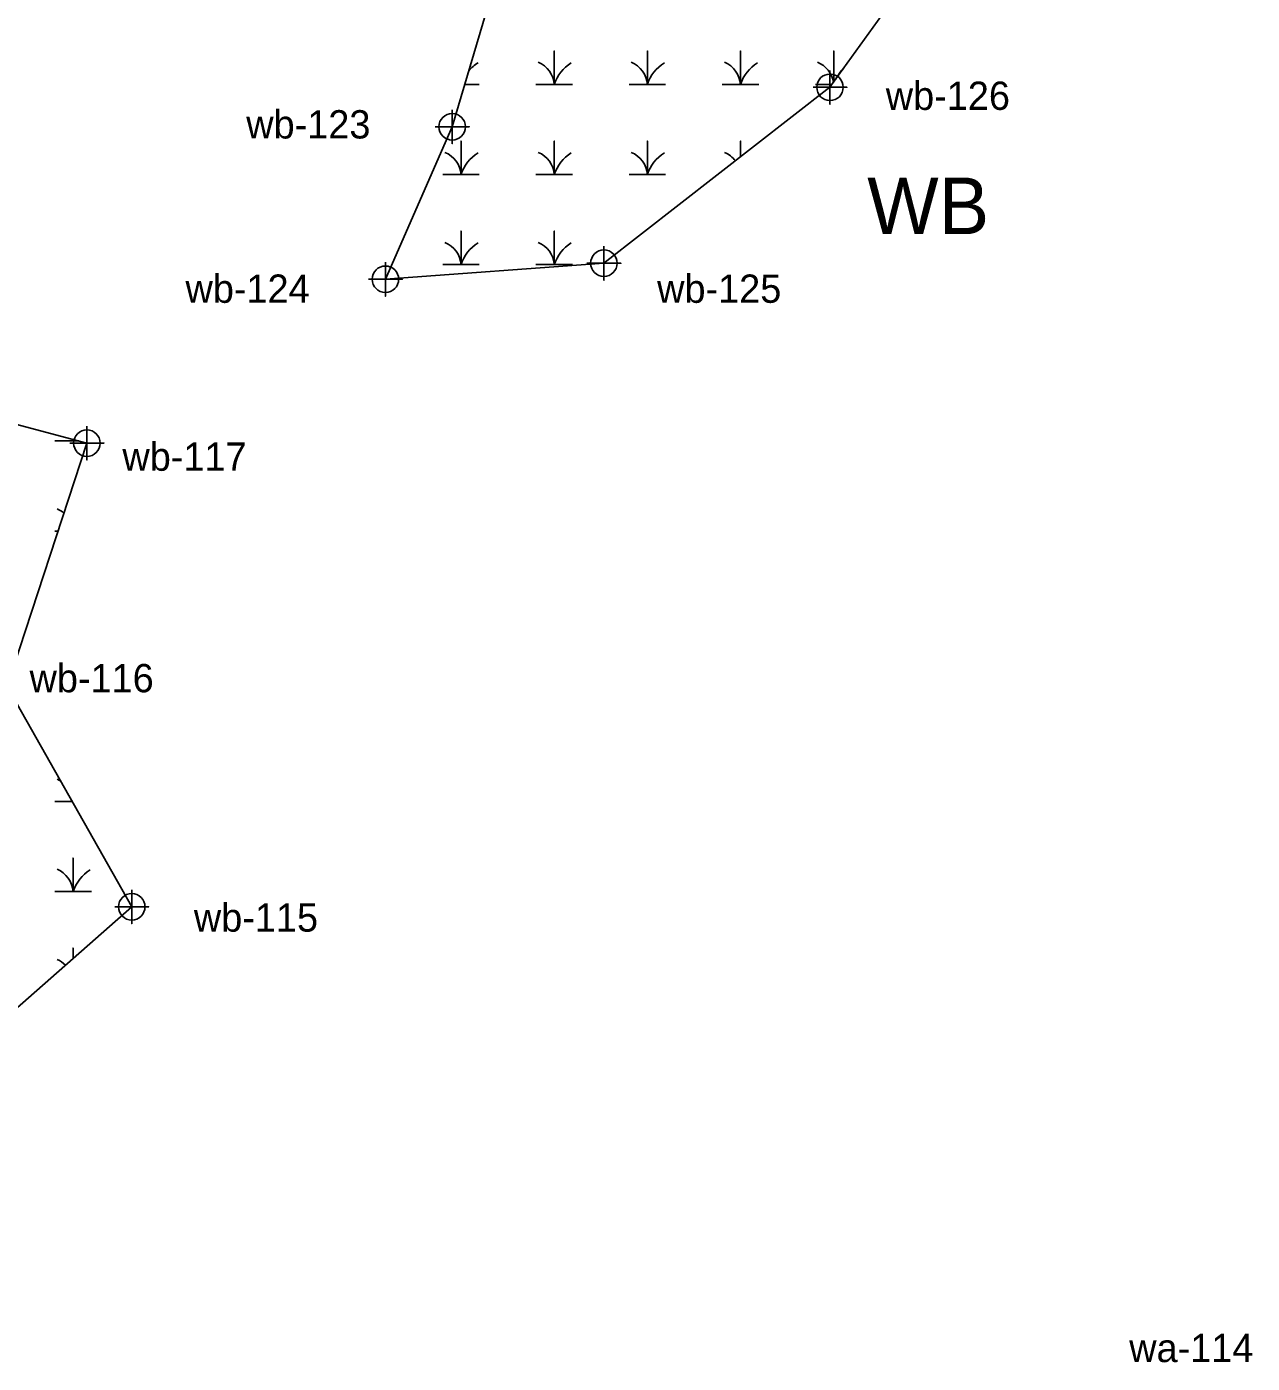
# Model space of a CAD drawing. Extents: x 2379288 to 2381905, y 330670 to 333511.
# Drawn here: x 2380668.2 to 2380884.6, y 332675.5 to 332911.6 of the extents above; entities that cross this region are included whole.
import ezdxf

# ---------------------------------------------------------------- set-up
doc = ezdxf.new("R2010")
doc.units = 0
for name, color, linetype in [('Exist Environmental Wetland Boundary', 7, 'Continuous'), ('Exist Environmental Wetland Boundary Cogo Number', 7, 'Continuous'), ('Exist Environmental Wetland Boundary Cogo Point CELL', 7, 'Continuous'), ('Exist Environmental Wetland Boundary Text', 7, 'Continuous'), ('Exist Hydro Swamp or Marsh', 7, 'Continuous')]:
    doc.layers.add(name, color=color, linetype=linetype)

msp = doc.modelspace()

# ---------------------------------------------------------------- linework, layer by layer
at = {"layer": 'Exist Environmental Wetland Boundary'}
for points in [[(2380770.18, 333002.77), (2380771.99, 332963.9), (2380813.28, 332972.8), (2380832.48, 332957.91), (2380839.06, 332941.31), (2380810.01, 332900.93), (2380770.09, 332869.86), (2380731.49, 332867.02), (2380743.29, 332893.96), (2380756.83, 332939.63), (2380739.11, 332942.35), (2380671.81, 332926.03)], [(2380604.8, 332868.97), (2380606.54, 332870.55), (2380633.85, 332850.01), (2380678.79, 332838.07), (2380664.67, 332795.06), (2380686.7, 332756.16), (2380626.94, 332703.59), (2380578.61, 332658.53)]]:
    msp.add_lwpolyline(points, dxfattribs=at)
at = {"layer": 'Exist Environmental Wetland Boundary Cogo Point CELL'}
for points in [[(2380810.01, 332903.93), (2380810.01, 332897.93), (2380810.01, 332900.93), (2380813.01, 332900.93), (2380807.01, 332900.93)], [(2380743.29, 332896.96), (2380743.29, 332890.96), (2380743.29, 332893.96), (2380746.29, 332893.96), (2380740.29, 332893.96)], [(2380770.08, 332872.86), (2380770.08, 332866.86), (2380770.08, 332869.86), (2380773.08, 332869.86), (2380767.08, 332869.86)], [(2380731.49, 332870.02), (2380731.49, 332864.02), (2380731.49, 332867.02), (2380734.49, 332867.02), (2380728.49, 332867.02)], [(2380678.78, 332841.07), (2380678.78, 332835.07), (2380678.78, 332838.07), (2380681.78, 332838.07), (2380675.78, 332838.07)], [(2380686.7, 332759.16), (2380686.7, 332753.16), (2380686.7, 332756.16), (2380689.7, 332756.16), (2380683.7, 332756.16)]]:
    msp.add_lwpolyline(points, dxfattribs=at)
for centre in [(2380810.01, 332900.93), (2380743.29, 332893.96), (2380770.08, 332869.86), (2380731.49, 332867.02), (2380678.78, 332838.07), (2380686.7, 332756.16)]:
    msp.add_circle(centre, 2.34, dxfattribs=at)
at = {"layer": 'Exist Hydro Swamp or Marsh'}
for p, q in [((2380745.51, 332901.43), (2380748.08, 332901.43)), ((2380807.43, 332901.43), (2380810.37, 332901.43)), ((2380673.12, 332822.53), (2380673.69, 332822.53)), ((2380673.12, 332774.78), (2380676.16, 332774.78))]:
    msp.add_line(p, q, dxfattribs=at)
for points in [[(2380758.08, 332901.43), (2380761.31, 332901.43), (2380761.31, 332907.35), (2380761.31, 332901.43), (2380764.53, 332901.43)], [(2380774.53, 332901.43), (2380777.76, 332901.43), (2380777.76, 332907.35), (2380777.76, 332901.43), (2380780.98, 332901.43)], [(2380790.98, 332901.43), (2380794.21, 332901.43), (2380794.21, 332907.35), (2380794.21, 332901.43), (2380797.43, 332901.43)], [(2380810.66, 332901.84), (2380810.66, 332907.35), (2380810.66, 332901.84)], [(2380741.63, 332885.52), (2380744.85, 332885.52), (2380744.85, 332891.43), (2380744.85, 332885.52), (2380748.08, 332885.52)], [(2380758.08, 332885.52), (2380761.31, 332885.52), (2380761.31, 332891.43), (2380761.31, 332885.52), (2380764.53, 332885.52)], [(2380774.53, 332885.52), (2380777.76, 332885.52), (2380777.76, 332891.43), (2380777.76, 332885.52), (2380780.98, 332885.52)], [(2380794.21, 332888.64), (2380794.21, 332891.43), (2380794.21, 332888.64)], [(2380741.63, 332869.6), (2380744.85, 332869.6), (2380744.85, 332875.52), (2380744.85, 332869.6), (2380748.08, 332869.6)], [(2380758.08, 332869.6), (2380761.31, 332869.6), (2380761.31, 332875.52), (2380761.31, 332869.6), (2380764.53, 332869.6)], [(2380673.12, 332838.45), (2380676.35, 332838.45), (2380676.35, 332838.72)], [(2380676.35, 332838.72), (2380676.35, 332838.45), (2380677.38, 332838.45)], [(2380673.12, 332758.86), (2380676.35, 332758.86), (2380676.35, 332764.78), (2380676.35, 332758.86), (2380679.57, 332758.86)], [(2380676.35, 332747.05), (2380676.35, 332748.86), (2380676.35, 332747.05)]]:
    msp.add_lwpolyline(points, dxfattribs=at)
for centre, radius, start, end in [((2380751.69, 332899.16), 7.21, 122.1274, 139.3248), ((2380756.71, 332901.1), 4.61, 4.1403, 67.535), ((2380768.15, 332899.16), 7.21, 122.1274, 161.6222), ((2380773.16, 332901.1), 4.61, 4.1403, 67.535), ((2380784.6, 332899.16), 7.21, 122.1274, 161.6222), ((2380789.61, 332901.1), 4.61, 4.1403, 67.535), ((2380801.05, 332899.16), 7.21, 122.1274, 161.6222), ((2380806.06, 332901.1), 4.61, 8.532, 67.535), ((2380817.5, 332899.16), 7.21, 135.1268, 153.4015), ((2380740.25, 332885.18), 4.61, 4.1403, 67.535), ((2380751.69, 332883.24), 7.21, 122.1274, 161.6222), ((2380756.71, 332885.18), 4.61, 4.1403, 67.535), ((2380768.15, 332883.24), 7.21, 122.1274, 161.6222), ((2380773.16, 332885.18), 4.61, 4.1403, 67.535), ((2380784.6, 332883.24), 7.21, 122.1274, 161.6222), ((2380789.61, 332885.18), 4.61, 36.6498, 67.535), ((2380740.25, 332869.27), 4.61, 4.1403, 67.535), ((2380751.69, 332867.33), 7.21, 122.1274, 161.6222), ((2380756.71, 332869.27), 4.61, 4.1403, 67.535), ((2380768.15, 332867.33), 7.21, 122.1274, 161.6222), ((2380671.75, 332838.11), 4.61, 4.1403, 7.6494), ((2380683.19, 332836.17), 7.21, 159.5165, 161.6222), ((2380671.75, 332822.2), 4.61, 49.6985, 67.535), ((2380671.75, 332774.44), 4.61, 59.2788, 67.535), ((2380671.75, 332758.53), 4.61, 4.1403, 67.535), ((2380683.19, 332756.59), 7.21, 122.1274, 161.6222), ((2380671.75, 332742.61), 4.61, 45.0205, 67.535)]:
    msp.add_arc(centre, radius, start, end, dxfattribs=at)

# ---------------------------------------------------------------- texts
at = {"layer": 'Exist Environmental Wetland Boundary Cogo Number'}
for s, p in [('wb-126', (2380819.86, 332896.94)), ('wb-123', (2380706.92, 332891.89)), ('wb-124', (2380696.19, 332862.86)), ('wb-125', (2380779.48, 332862.86)), ('wb-117', (2380685.05, 332833.19)), ('wb-116', (2380668.65, 332794.06)), ('wb-115', (2380697.67, 332751.77)), ('wa-114', (2380862.85, 332675.73))]:
    msp.add_text(s, height=5, dxfattribs=at).set_placement(p)
at = {"layer": 'Exist Environmental Wetland Boundary Text'}
msp.add_text('WB', height=10, dxfattribs=at).set_placement((2380816.58, 332874.99))

doc.saveas('drawing.dxf')
